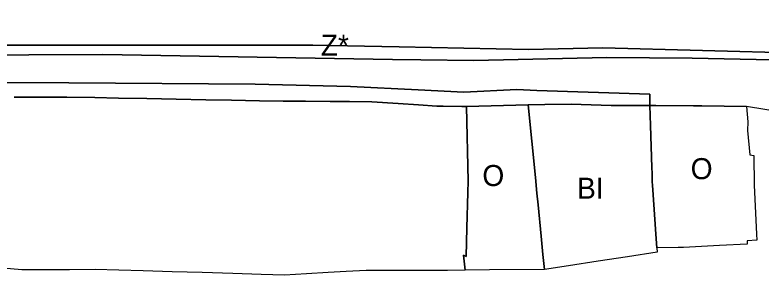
# Model space of a CAD drawing. Extents: x -521621 to -516769, y -1190068 to -1185078.
# Drawn here: x -519302 to -518947.5, y -1187294.3 to -1187170.7 of the extents above; entities that cross this region are included whole.
import ezdxf

# ---------------------------------------------------------------- set-up
doc = ezdxf.new("R2010")
doc.units = 0
for name, color, linetype in [('bydleni_s', 7, 'Continuous'), ('s_zelen_s', 7, 'Continuous'), ('v_infrastr_s', 7, 'Continuous'), ('voda_s', 7, 'Continuous')]:
    doc.layers.add(name, color=color, linetype=linetype)

msp = doc.modelspace()

# ---------------------------------------------------------------- linework, layer by layer
at = {"layer": 'bydleni_s'}
for points in [[(-519302.43, -1187209.83), (-519291.24, -1187209.8)], [(-519291.24, -1187209.8), (-519277.36, -1187209.76)], [(-519277.36, -1187209.76), (-519264.05, -1187210.02)], [(-519264.05, -1187210.02), (-519252.76, -1187210.23)], [(-519252.76, -1187210.23), (-519239.33, -1187210.49)], [(-519239.33, -1187210.49), (-519225.45, -1187210.76)], [(-519225.45, -1187210.76), (-519211.29, -1187211.03)], [(-519211.29, -1187211.03), (-519199.08, -1187211.27)], [(-519199.08, -1187211.27), (-519185.92, -1187211.52)], [(-519185.92, -1187211.52), (-519174.57, -1187211.63)], [(-519174.57, -1187211.63), (-519164.01, -1187211.73)], [(-519164.01, -1187211.73), (-519152.29, -1187211.85)], [(-519152.29, -1187211.85), (-519143.02, -1187211.94)], [(-519143.02, -1187211.94), (-519132.53, -1187212.04)], [(-519132.53, -1187212.04), (-519120.03, -1187212.83)], [(-519120.03, -1187212.83), (-519110.24, -1187213.45)], [(-519110.24, -1187213.45), (-519101.65, -1187214), (-519098.59, -1187214.07)], [(-519098.59, -1187214.07), (-519089.79, -1187214.26), (-519087.45, -1187214.31), (-519086.71, -1187249.65)], [(-519054.78, -1187247.99), (-519058.2, -1187213.46), (-519050.3, -1187213.34)], [(-519050.3, -1187213.34), (-519037.75, -1187213.15)], [(-519037.75, -1187213.15), (-519018.77, -1187213.69)], [(-519018.77, -1187213.69), (-519000.33, -1187213.77), (-519000.03, -1187223.31), (-518999.42, -1187243.19)], [(-518999.42, -1187243.19), (-518999.33, -1187246.11), (-518999.21, -1187249.98), (-518999.1, -1187251.56), (-518997.34, -1187277.07), (-518997.05, -1187281.35), (-518996.9, -1187283.45), (-519010.97, -1187285.6)], [(-519086.71, -1187249.65), (-519086.85, -1187255.02), (-519087.29, -1187271.94), (-519087.64, -1187285.45), (-519088.87, -1187284.84), (-519088.12, -1187292.01), (-519096.59, -1187292.09), (-519099.68, -1187292.09)], [(-519039.03, -1187289.89), (-519050.45, -1187291.63), (-519051.16, -1187284.46), (-519052.01, -1187275.9), (-519053.49, -1187260.97), (-519054.04, -1187255.41), (-519054.78, -1187247.99)], [(-519024.92, -1187287.73), (-519039.03, -1187289.89)], [(-519010.97, -1187285.6), (-519024.92, -1187287.73)], [(-519298.75, -1187291.89), (-519309.64, -1187290.85)], [(-519287.41, -1187291.84), (-519298.75, -1187291.89)], [(-519276.06, -1187291.79), (-519287.41, -1187291.84)], [(-519263.85, -1187291.73), (-519276.06, -1187291.79)], [(-519252.62, -1187292.03), (-519263.85, -1187291.73)], [(-519241.06, -1187292.35), (-519252.62, -1187292.03)], [(-519227.26, -1187292.72), (-519241.06, -1187292.35)], [(-519135.11, -1187292.07), (-519144.61, -1187292.62)], [(-519121.24, -1187292.08), (-519135.11, -1187292.07)], [(-519111.1, -1187292.08), (-519121.24, -1187292.08)], [(-519099.68, -1187292.09), (-519111.1, -1187292.08)], [(-519213.13, -1187293.1), (-519227.26, -1187292.72)], [(-519198.51, -1187293.55), (-519213.13, -1187293.1)], [(-519185.01, -1187293.96), (-519198.51, -1187293.55)], [(-519173.9, -1187294.3), (-519185.01, -1187293.96)], [(-519163.56, -1187293.71), (-519173.9, -1187294.3)], [(-519153.24, -1187293.11), (-519163.56, -1187293.71)], [(-519144.61, -1187292.62), (-519153.24, -1187293.11)]]:
    msp.add_lwpolyline(points, dxfattribs=at)
at = {"layer": 's_zelen_s'}
for points in [[(-519976.25, -1186969.59), (-519973.89, -1186964.34), (-519945.18, -1186982.09), (-519941.17, -1186985.33), (-519876.04, -1187044.95), (-519872.07, -1187048.29), (-519870.88, -1187049.41), (-519831.64, -1187086.03), (-519782.87, -1187121.37), (-519783.03, -1187122.14), (-519711.27, -1187163.96), (-519691.98, -1187171.68), (-519636.11, -1187188.04), (-519566.51, -1187196.52), (-519488.58, -1187203.01), (-519374.38, -1187202.7), (-519363.08, -1187202.74), (-519276.38, -1187203.01), (-519187.84, -1187203.66), (-519142.54, -1187204.74), (-519110.53, -1187206.31), (-519088.84, -1187207.37)], [(-519122.7, -1187191.89), (-519260.22, -1187189.55), (-519365.76, -1187190.07), (-519366.84, -1187184.99), (-519311.33, -1187185.14), (-519272.36, -1187185.14), (-519160.43, -1187185.04), (-519119.53, -1187185.92)], [(-519119.53, -1187185.92), (-519058.07, -1187187.23), (-519022.79, -1187186.43), (-518928.1, -1187188.93), (-518907.27, -1187187.83), (-518907.56, -1187188.77), (-518907.91, -1187189.9), (-518908.24, -1187190.95), (-518927.11, -1187192.31), (-518980.23, -1187191.22), (-519020.8, -1187190.92), (-519084.08, -1187192.31), (-519109.21, -1187192.12), (-519122.7, -1187191.89)], [(-519088.84, -1187207.37), (-519063.53, -1187206.13), (-519054.11, -1187206.59), (-519000.33, -1187208.37), (-519000.33, -1187213.77), (-519018.77, -1187213.69), (-519037.75, -1187213.15), (-519050.3, -1187213.34), (-519058.2, -1187213.46), (-519087.45, -1187214.31), (-519089.79, -1187214.26)], [(-519089.79, -1187214.26), (-519098.59, -1187214.07), (-519101.65, -1187214), (-519110.24, -1187213.45), (-519120.03, -1187212.83), (-519132.53, -1187212.04), (-519143.02, -1187211.94), (-519152.29, -1187211.85), (-519164.01, -1187211.73), (-519174.57, -1187211.63), (-519185.92, -1187211.52), (-519199.08, -1187211.27), (-519211.29, -1187211.03), (-519225.45, -1187210.76), (-519239.33, -1187210.49), (-519252.76, -1187210.23), (-519264.05, -1187210.02), (-519277.36, -1187209.76), (-519291.24, -1187209.8), (-519302.43, -1187209.83)]]:
    msp.add_lwpolyline(points, dxfattribs=at)
at = {"layer": 'v_infrastr_s'}
for p, q in [((-518953.96, -1187225.65), (-518952.84, -1187237.27)), ((-518950.76, -1187251.58), (-518949.68, -1187274.83)), ((-519039.03, -1187289.89), (-519050.45, -1187291.63))]:
    msp.add_line(p, q, dxfattribs=at)
for points in [[(-519272.36, -1187185.14), (-519311.33, -1187185.14)], [(-519160.43, -1187185.04), (-519272.36, -1187185.14)], [(-519119.53, -1187185.92), (-519160.43, -1187185.04)], [(-519058.07, -1187187.23), (-519119.53, -1187185.92)], [(-519022.79, -1187186.43), (-519058.07, -1187187.23)], [(-518928.1, -1187188.93), (-519022.79, -1187186.43)], [(-519086.71, -1187249.65), (-519087.45, -1187214.31), (-519058.2, -1187213.46), (-519054.78, -1187247.99)], [(-519000.03, -1187223.31), (-519000.33, -1187213.77), (-518997.62, -1187213.78)], [(-518997.62, -1187213.78), (-518979.65, -1187213.85), (-518975.71, -1187213.9)], [(-518975.71, -1187213.9), (-518954.5, -1187214.16), (-518953.8, -1187221.45), (-518953.96, -1187225.65)], [(-518926.85, -1187218.28), (-518938.06, -1187216.93), (-518954.5, -1187214.16), (-518953.8, -1187221.45), (-518953.96, -1187225.65)], [(-518999.42, -1187243.19), (-519000.03, -1187223.31)], [(-518953.96, -1187225.65), (-518952.84, -1187237.27), (-518951.06, -1187237.57), (-518950.76, -1187251.58)], [(-518952.84, -1187237.27), (-518951.06, -1187237.57), (-518950.76, -1187251.58)], [(-518999.1, -1187251.56), (-518999.21, -1187249.98), (-518999.33, -1187246.11), (-518999.42, -1187243.19)], [(-519087.29, -1187271.94), (-519086.85, -1187255.02), (-519086.71, -1187249.65)], [(-519054.78, -1187247.99), (-519054.04, -1187255.41), (-519053.49, -1187260.97)], [(-518986.98, -1187281.24), (-518997.05, -1187281.35), (-518997.34, -1187277.07), (-518999.1, -1187251.56)], [(-518950.76, -1187251.58), (-518949.68, -1187274.83), (-518949.54, -1187277.8), (-518954.09, -1187278.07), (-518954.08, -1187279.56)], [(-519053.49, -1187260.97), (-519052.01, -1187275.9), (-519051.16, -1187284.46), (-519050.45, -1187291.63), (-519076.52, -1187291.89)], [(-519076.52, -1187291.89), (-519088.12, -1187292.01), (-519088.87, -1187284.84), (-519087.64, -1187285.45), (-519087.29, -1187271.94)], [(-518954.09, -1187278.07), (-518954.08, -1187279.56), (-518967.27, -1187280.28)], [(-518949.68, -1187274.83), (-518949.54, -1187277.8), (-518954.09, -1187278.07)], [(-518984.39, -1187281.21), (-518986.98, -1187281.24), (-518997.05, -1187281.35), (-518996.9, -1187283.45)], [(-518984.39, -1187281.21), (-518986.98, -1187281.24)], [(-518954.08, -1187279.56), (-518967.27, -1187280.28), (-518984.39, -1187281.21)], [(-518967.27, -1187280.28), (-518984.39, -1187281.21)], [(-518996.9, -1187283.45), (-519010.97, -1187285.6), (-519024.92, -1187287.73), (-519039.03, -1187289.89)], [(-519050.45, -1187291.63), (-519076.52, -1187291.89), (-519088.12, -1187292.01), (-519096.59, -1187292.09), (-519099.68, -1187292.09), (-519111.1, -1187292.08), (-519121.24, -1187292.08), (-519135.11, -1187292.07), (-519144.61, -1187292.62), (-519153.24, -1187293.11), (-519163.56, -1187293.71), (-519173.9, -1187294.3), (-519185.01, -1187293.96), (-519198.51, -1187293.55), (-519213.13, -1187293.1), (-519227.26, -1187292.72), (-519241.06, -1187292.35), (-519252.62, -1187292.03), (-519263.85, -1187291.73), (-519276.06, -1187291.79), (-519287.41, -1187291.84), (-519298.75, -1187291.89), (-519309.64, -1187290.85)]]:
    msp.add_lwpolyline(points, dxfattribs=at)
at = {"layer": 'voda_s'}
for points in [[(-519582.24, -1187178.82), (-519519.49, -1187187.61), (-519366.03, -1187190.07), (-519365.76, -1187190.07), (-519260.22, -1187189.55), (-519122.7, -1187191.89), (-519109.21, -1187192.12), (-519084.08, -1187192.31), (-519020.8, -1187190.92), (-518980.23, -1187191.22), (-518927.11, -1187192.31), (-518908.24, -1187190.95)], [(-518954.5, -1187214.16), (-518975.71, -1187213.9), (-518979.65, -1187213.85), (-518997.62, -1187213.78), (-519000.33, -1187213.77), (-519000.33, -1187208.37), (-519054.11, -1187206.59), (-519063.53, -1187206.13), (-519088.84, -1187207.37), (-519110.53, -1187206.31), (-519142.54, -1187204.74), (-519187.84, -1187203.66), (-519276.38, -1187203.01), (-519363.08, -1187202.74), (-519374.38, -1187202.7), (-519488.58, -1187203.01), (-519566.51, -1187196.52)], [(-518938.06, -1187216.93), (-518954.5, -1187214.16)]]:
    msp.add_lwpolyline(points, dxfattribs=at)

# ---------------------------------------------------------------- texts
at = {"layer": 'bydleni_s'}
msp.add_text('BI', height=10, dxfattribs=at).set_placement((-519034.97, -1187258.04))
at = {"layer": 's_zelen_s'}
msp.add_text('Z*', height=10, dxfattribs=at).set_placement((-519156.72, -1187190.17))
at = {"layer": 'v_infrastr_s'}
for p in [(-518980.99, -1187248.76), (-519079.96, -1187252.02)]:
    msp.add_text('O', height=10, dxfattribs=at).set_placement(p)

doc.saveas('drawing.dxf')
